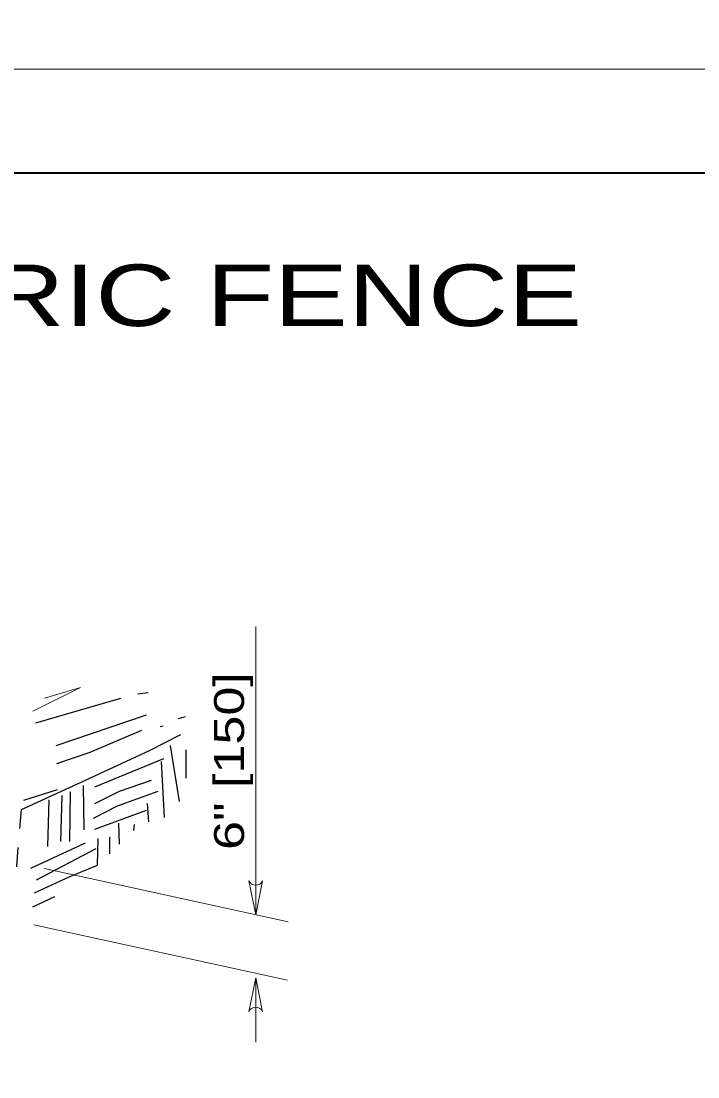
# Model space of a CAD drawing. Extents: x 1083.1 to 1117.1, y 672.5 to 716.5.
# Drawn here: x 1102.49 to 1106.01, y 689.26 to 694.76 of the extents above; entities that cross this region are included whole.
import ezdxf
from ezdxf.enums import TextEntityAlignment as Align

# ---------------------------------------------------------------- set-up
doc = ezdxf.new("R2010")
doc.units = 0
doc.header["$LTSCALE"] = 0.062
doc.linetypes.add('DOTTED', pattern=[1.5, 0.3, -1.2])
doc.linetypes.add('LONG_DASHED', pattern=[7.5, 6, -1.5])
doc.layers.add('1', color=7, linetype='Continuous', lineweight=13)

msp = doc.modelspace()

# ---------------------------------------------------------------- linework, layer by layer
at = {"layer": '1', "lineweight": 25}
for p, q in [((1085.14617, 693.96842), (1116.64617, 693.96842)), ((1103.09342, 691.25533), (1103.14658, 691.26292)), ((1102.56133, 691.104), (1103.00475, 691.23267)), ((1102.66775, 690.98675), (1103.1395, 691.14567)), ((1103.30625, 691.12675), (1103.34167, 691.13808)), ((1103.15425, 690.96033), (1103.31683, 691.0435)), ((1103.21042, 691.08508), (1103.22467, 691.08892)), ((1103.30975, 690.6955), (1103.26367, 690.98675)), ((1103.34525, 690.81658), (1103.34525, 690.96408)), ((1102.86992, 690.77117), (1103.22817, 690.91867)), ((1103.23175, 690.61233), (1103.21758, 690.90358)), ((1102.81317, 690.548), (1102.80967, 690.77875)), ((1102.67317, 690.75558), (1102.49833, 690.70108)), ((1102.69258, 690.4875), (1102.69967, 690.72583)), ((1102.73967, 690.48742), (1102.74225, 690.74467)), ((1102.62525, 690.461), (1102.63233, 690.70308)), ((1103.15017, 690.58967), (1103.14308, 690.68417)), ((1102.86992, 690.55183), (1103.1395, 690.65017)), ((1102.99767, 690.47242), (1102.99408, 690.58208)), ((1103.07217, 690.54425), (1103.07567, 690.5745)), ((1102.948, 690.42317), (1102.948, 690.51017)), ((1102.5365, 690.34758), (1102.82033, 690.47992)), ((1102.56492, 690.28708), (1102.87708, 690.44967)), ((1102.54717, 690.14708), (1102.66067, 690.20008))]:
    msp.add_line(p, q, dxfattribs=at)
at = {"layer": '1'}
for p, q in [((1103.7075, 690.10542), (1103.7075, 691.607)), ((1102.60767, 690.34575), (1103.877, 690.06842)), ((1102.551, 690.05325), (1103.87325, 689.76442)), ((1103.7075, 689.44242), (1103.7075, 689.77733))]:
    msp.add_line(p, q, dxfattribs=at)
at = {"layer": '1', "linetype": 'DOTTED', "lineweight": 25}
msp.add_line((1102.46258, 690.35517), (1102.48683, 690.65383), dxfattribs=at)
at = {"layer": '1', "linetype": 'LONG_DASHED'}
for points in [[(1083.12642, 694.50825), (1117.12642, 694.50825), (1117.12642, 716.50825), (1083.12642, 716.50825)], [(1083.12642, 672.50825), (1117.12642, 672.50825), (1117.12642, 694.50825), (1083.12642, 694.50825)]]:
    msp.add_lwpolyline(points, close=True, dxfattribs=at)
at = {"layer": '1', "lineweight": 40}
msp.add_lwpolyline([(1085.14617, 693.96842), (1116.64617, 693.96842), (1116.64617, 672.96842), (1085.14617, 672.96842)], close=True, dxfattribs=at)
at = {"layer": '1'}
for points in [[(1102.54717, 691.16458), (1102.7955, 691.28933), (1102.6075, 691.23267)], [(1103.74292, 690.28242), (1103.7075, 690.10542), (1103.67208, 690.28242), (1103.67225, 690.28242)], [(1103.67208, 689.60033), (1103.7075, 689.77733), (1103.74292, 689.60033), (1103.74275, 689.60033)]]:
    msp.add_lwpolyline(points, dxfattribs=at)
at = {"layer": '1', "lineweight": 25}
for points in [[(1102.67133, 690.89225), (1102.84508, 690.95275), (1103.11467, 691.06617)], [(1102.48683, 690.65383), (1102.82083, 690.80525), (1103.15425, 690.96033)], [(1102.86992, 690.68417), (1102.99767, 690.7485), (1103.16433, 690.80525)], [(1102.86283, 690.6085), (1102.987, 690.67283), (1103.19983, 690.7485)], [(1102.55425, 690.219), (1102.73517, 690.30217), (1102.88417, 690.36267), (1102.88767, 690.50267)]]:
    msp.add_lwpolyline(points, dxfattribs=at)
at = {"layer": '1'}
for centre, start, end in [((1103.70759, 690.29683), 202.08789, 337.91402), ((1103.70742, 689.58591), 22.08789, 157.91402)]:
    msp.add_arc(centre, 0.0382, start, end, dxfattribs=at)

# ---------------------------------------------------------------- texts
at = {"layer": '1', "width": 1.35}
msp.add_text('PERIMETER FILTER FABRIC FENCE', height=0.32, dxfattribs=at).set_placement((1100.44883, 693.17075), align=Align.CENTER)
at = {"layer": '1', "width": 1.3}
msp.add_text('6" [150]', height=0.156, rotation=90, dxfattribs=at).set_placement((1103.64683, 690.44292))

doc.saveas('drawing.dxf')
